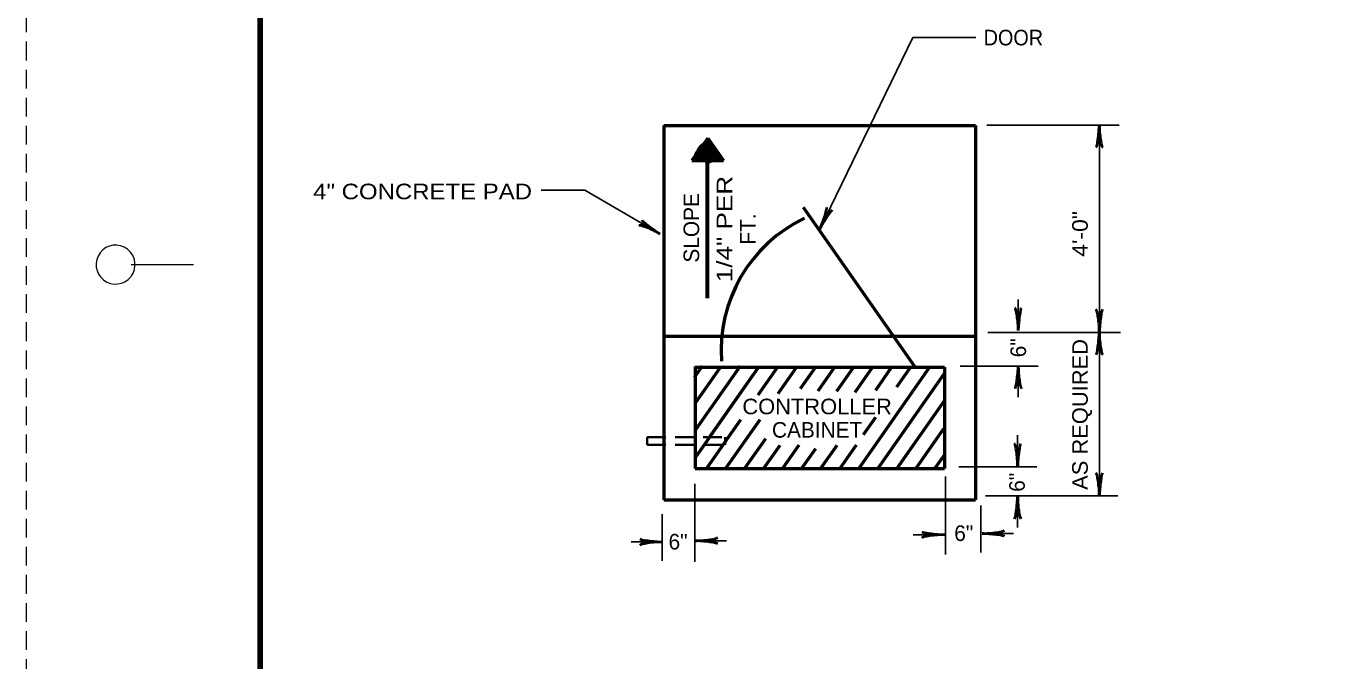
# Model space of a CAD drawing. Extents: x -560 to 120, y 26 to 466.
# Drawn here: x -559.8 to -392.1, y 112.8 to 194.2 of the extents above; entities that cross this region are included whole.
import ezdxf
from ezdxf.enums import TextEntityAlignment as Align

# ---------------------------------------------------------------- set-up
doc = ezdxf.new("R2010")
doc.units = 0
doc.header["$LTSCALE"] = 0.8
doc.linetypes.add('MEDIUM_DASHED', pattern=[4.5, 3, -1.5])
doc.layers.add('1', color=7, linetype='Continuous', lineweight=53)
doc.layers.add('61', color=7, linetype='Continuous', lineweight=35)

msp = doc.modelspace()

# ---------------------------------------------------------------- linework, layer by layer
at = {"layer": '1', "linetype": 'MEDIUM_DASHED', "lineweight": 13}
msp.add_line((-559.7809, 465.8427), (-559.8409, 25.8027), dxfattribs=at)
at = {"layer": '1'}
for p, q in [((-477.9601, 181.4815), (-477.9601, 133.4815)), ((-477.9601, 181.4815), (-472.0546, 181.4815)), ((-473.9601, 181.4815), (-473.9601, 181.3655)), ((-473.8417, 181.4815), (-437.9601, 181.4815)), ((-437.9601, 181.4815), (-437.9601, 133.4815)), ((-472.3459, 179.8789), (-474.3775, 176.9776)), ((-472.3459, 179.8789), (-470.3143, 176.9776)), ((-474.3775, 176.9776), (-470.3143, 176.9776)), ((-445.7124, 150.4778), (-460.0518, 170.9567)), ((-477.9601, 154.4815), (-437.9601, 154.4815)), ((-473.0564, 150.6275), (-474.0715, 149.1778)), ((-473.9601, 150.5942), (-473.9601, 150.4388)), ((-473.9601, 150.4815), (-473.8417, 150.4815)), ((-473.9601, 150.4815), (-441.9601, 150.4815)), ((-473.9601, 150.4815), (-473.9601, 137.4815)), ((-465.8339, 150.4815), (-473.9601, 138.8762)), ((-470.8374, 150.3097), (-473.941, 145.8773)), ((-468.1692, 150.6333), (-473.905, 142.4417)), ((-466.5309, 149.4861), (-472.2667, 141.2946)), ((-463.3923, 150.4815), (-465.9038, 146.895)), ((-460.9509, 150.4815), (-463.3357, 147.0756)), ((-458.5093, 150.4815), (-460.4595, 147.6964)), ((-456.0677, 150.4815), (-458.2222, 147.4047)), ((-453.6262, 150.4815), (-455.795, 147.3841)), ((-451.1846, 150.4815), (-453.4482, 147.2488)), ((-443.8601, 150.4815), (-452.9627, 137.4815)), ((-448.7431, 150.4815), (-450.8202, 147.5151)), ((-441.9601, 149.708), (-450.5212, 137.4815)), ((-446.3015, 150.4815), (-448.1046, 147.9064)), ((-441.9601, 150.4815), (-441.9601, 137.4815)), ((-441.9601, 146.2211), (-448.0796, 137.4815)), ((-468.1164, 143.7349), (-472.4951, 137.4815)), ((-465.6689, 143.7434), (-470.0535, 137.4815)), ((-450.8174, 144.032), (-452.373, 141.8105)), ((-464.9432, 141.2928), (-467.612, 137.4815)), ((-442.0678, 142.5806), (-445.6382, 137.4815)), ((-463.0967, 140.4432), (-465.1705, 137.4815)), ((-460.6257, 140.4852), (-462.7289, 137.4815)), ((-458.5198, 140.0057), (-460.2873, 137.4815)), ((-455.7641, 140.4545), (-457.8458, 137.4815)), ((-453.2858, 140.5069), (-455.4042, 137.4815)), ((-441.9601, 139.2473), (-443.1312, 137.5747)), ((-473.9601, 137.4815), (-441.9601, 137.4815)), ((-477.9601, 133.4815), (-437.9601, 133.4815))]:
    msp.add_line(p, q, dxfattribs=at)
at = {"layer": '1', "lineweight": 25}
for p, q in [((-436.5237, 181.5331), (-419.5237, 181.5331)), ((-432.4829, 155.1907), (-432.4829, 159.1907)), ((-436.3682, 154.9578), (-419.3682, 154.9578)), ((-439.9427, 150.6062), (-429.9427, 150.6062)), ((-432.4829, 146.6431), (-432.4829, 150.6431)), ((-432.5606, 137.7846), (-432.5606, 141.7846)), ((-440.0981, 137.7071), (-430.0981, 137.7071)), ((-441.8077, 136.4638), (-441.8077, 126.4637)), ((-473.9778, 135.5312), (-473.9778, 125.5312)), ((-437.3007, 132.7339), (-437.3007, 126.7339)), ((-436.6791, 133.9772), (-419.6791, 133.9772)), ((-432.5606, 129.9363), (-432.5606, 133.9363)), ((-478.1739, 131.646), (-478.1739, 125.646)), ((-478.1739, 128.0715), (-482.1739, 128.0715)), ((-469.9372, 128.2269), (-473.9372, 128.2269)), ((-441.9631, 129.004), (-445.9631, 129.004)), ((-433.1046, 129.1594), (-437.1046, 129.1594))]:
    msp.add_line(p, q, dxfattribs=at)
at = {"layer": '1', "lineweight": 60}
msp.add_line((-472.4237, 179.3572), (-472.4237, 159.3572), dxfattribs=at)
at = {"layer": '1', "linetype": 'MEDIUM_DASHED', "lineweight": 35}
for p, q in [((-480.1165, 141.5145), (-470.1165, 141.5145)), ((-480.1165, 141.5145), (-480.1165, 140.5145)), ((-470.1165, 141.5145), (-470.1165, 140.5145)), ((-480.1165, 140.5145), (-470.1165, 140.5145))]:
    msp.add_line(p, q, dxfattribs=at)
at = {"layer": '1', "lineweight": 25}
for points in [[(-457.9705, 168.2067), (-446.0037, 192.7618), (-437.9209, 192.7618)], [(-422.0704, 181.5722), (-422.0704, 154.9968), (-422.0704, 134.0139)], [(-478.4848, 167.5852), (-488.1203, 173.1799), (-493.7173, 173.1799)]]:
    msp.add_lwpolyline(points, dxfattribs=at)
at = {"layer": '1'}
msp.add_arc((-451.8151, 152.622), 18.8127, 115.56181, 184.16724, dxfattribs=at)
at = {"layer": '1', "lineweight": 40}
for centre, major_axis, ratio, start_param, end_param in [((-422.282, 180.4517), (-0.1757, -1.7565), 0.07063, 6.28230741, 8.55970261), ((-422.282, 180.4517), (-0.1757, -1.7565), 0.07063, 6.28230741, 8.55970261), ((-421.7941, 180.481), (-0.1562, 1.7857), 0.122415, 0.89635335, 3.14159265), ((-421.7941, 180.481), (-0.1562, 1.7857), 0.122415, 0.89635335, 3.14159265), ((-457.7408, 169.3087), (-0.6419, -1.6736), 0.122415, 0.89635335, 3.14159265), ((-457.2894, 169.1213), (0.9274, 1.502), 0.07063, 6.28230741, 8.55970261), ((-479.5672, 167.8942), (1.6227, -0.7616), 0.122415, 0.89635335, 3.14159265), ((-479.3476, 168.3308), (1.4308, -1.0339), 0.07063, 3.14071475, 5.41810995), ((-432.7592, 156.2819), (0.1562, -1.7857), 0.122415, 0.89635335, 3.14159265), ((-432.2713, 156.3112), (0.1757, 1.7565), 0.07063, 6.28230741, 8.55970261), ((-422.3467, 156.088), (0.1562, -1.7857), 0.122415, 0.89635335, 3.14159265), ((-421.8588, 156.1173), (0.1757, 1.7565), 0.07063, 6.28230741, 8.55970261), ((-422.282, 153.8763), (-0.1757, -1.7565), 0.07063, 6.28230741, 8.55970261), ((-421.7941, 153.9056), (-0.1562, 1.7857), 0.122415, 0.89635335, 3.14159265), ((-432.6945, 149.5226), (-0.1757, -1.7565), 0.07063, 6.28230741, 8.55970261), ((-432.2066, 149.5519), (-0.1562, 1.7857), 0.122415, 0.89635335, 3.14159265), ((-432.8369, 138.8758), (0.1562, -1.7857), 0.122415, 0.89635335, 3.14159265), ((-432.349, 138.9051), (0.1757, 1.7565), 0.07063, 6.28230741, 8.55970261), ((-422.3467, 135.1051), (0.1562, -1.7857), 0.122415, 0.89635335, 3.14159265), ((-421.8588, 135.1344), (0.1757, 1.7565), 0.07063, 6.28230741, 8.55970261), ((-432.7722, 132.8158), (-0.1757, -1.7565), 0.07063, 6.28230741, 8.55970261), ((-432.2843, 132.8451), (-0.1562, 1.7857), 0.122415, 0.89635335, 3.14159265), ((-443.0836, 129.2156), (1.7565, -0.1757), 0.07063, 3.14071475, 5.41810995), ((-436.0134, 129.4357), (-1.7857, -0.1562), 0.122415, 0.89635335, 3.14159265), ((-479.2651, 127.7952), (1.7857, 0.1562), 0.122415, 0.89635335, 3.14159265), ((-479.2944, 128.2831), (1.7565, -0.1757), 0.07063, 3.14071475, 5.41810995), ((-472.8167, 128.0153), (1.7565, -0.1757), 0.07063, 6.28230741, 8.55970261), ((-472.846, 128.5032), (-1.7857, -0.1562), 0.122415, 0.89635335, 3.14159265), ((-443.0543, 128.7277), (1.7857, 0.1562), 0.122415, 0.89635335, 3.14159265), ((-435.9841, 128.9478), (1.7565, -0.1757), 0.07063, 6.28230741, 8.55970261)]:
    msp.add_ellipse(centre, major_axis=major_axis, ratio=ratio, start_param=start_param, end_param=end_param, dxfattribs=at)
at = {"layer": '1'}
msp.add_spline([(-472.4237, 179.2796), (-472.4237, 179.0464), (-472.4237, 179.5127), (-472.346, 178.4248), (-472.5791, 178.4248), (-472.5791, 178.891), (-472.6568, 178.9688), (-472.9677, 178.4248), (-473.3562, 177.8032), (-473.4338, 177.2592), (-473.5892, 177.2592), (-473.7447, 177.2592), (-473.9001, 177.1815), (-473.5892, 177.7254), (-473.9001, 177.2592), (-472.7345, 179.0464), (-472.1906, 178.5025), (-471.9574, 178.6579), (-471.6467, 178.1917), (-471.5689, 177.9586), (-471.8021, 178.3471), (-472.346, 178.8133), (-471.9574, 178.9688), (-471.8021, 178.7356), (-471.6467, 178.0362), (-471.4912, 177.8032), (-471.2581, 177.3369), (-471.1027, 177.1815), (-471.2581, 177.8808), (-471.5689, 178.114), (-471.025, 177.4147), (-470.9472, 177.2592), (-471.6467, 177.4147), (-472.2682, 177.8032), (-472.5014, 178.114), (-472.6568, 178.1917), (-472.7345, 177.8808), (-472.8123, 177.4923), (-472.9677, 177.4147), (-472.9677, 177.3369), (-472.0352, 178.1917), (-472.8899, 178.0362), (-472.9677, 177.4147), (-472.5791, 177.4923), (-472.1906, 177.4923), (-471.8021, 177.9586), (-471.7243, 177.8808), (-472.2682, 177.57), (-472.1906, 177.1038), (-471.9574, 177.1038), (-471.8798, 177.6478), (-473.1231, 177.4923), (-473.2784, 176.9484), (-472.9677, 177.3369), (-472.8123, 177.1038), (-471.4912, 177.3369), (-471.4912, 177.57), (-471.8021, 178.2694), (-472.1128, 178.5025), (-472.0352, 178.0362), (-471.5689, 178.0362), (-472.4237, 178.5025), (-472.8123, 178.2694), (-472.2682, 178.0362), (-472.1906, 179.1242), (-471.5689, 178.114), (-471.2581, 177.57), (-471.025, 177.3369), (-471.7243, 177.8032), (-472.4237, 178.5025), (-470.7918, 177.0261), (-471.4912, 178.2694), (-472.4237, 178.3471), (-472.4237, 178.7356), (-472.7345, 177.4923), (-472.8123, 177.3369)], degree=3, dxfattribs=at)
at = {"layer": '61', "lineweight": 13}
msp.add_line((-546.3609, 163.6627), (-538.3609, 163.6627), dxfattribs=at)
at = {"layer": '61', "lineweight": 158}
msp.add_lwpolyline([(109.2591, 455.8427), (-529.7809, 455.8427), (-529.7809, 35.8227)], dxfattribs=at)
at = {"layer": '61', "lineweight": 13}
msp.add_arc((-548.3632, 163.644), 2.5, 322.67175, 321.71615, dxfattribs=at)

# ---------------------------------------------------------------- texts
at = {"layer": '1'}
for s, width, p in [('DOOR', 0.95, (-433.1045, 191.7618)), ('4" CONCRETE PAD', 1.15, (-508.9454, 172.0245)), ('CONTROLLER', 1.05, (-458.3006, 144.4506))]:
    msp.add_text(s, height=2, dxfattribs=dict(at, width=width)).set_placement(p, align=Align.CENTER)
for s, width, p in [('1/4" PER', 1.25, (-469.1939, 168.2067)), ('4\'-0"', 1.1, (-423.557, 167.5852)), ('AS REQUIRED', 1.05, (-423.557, 144.4288))]:
    msp.add_text(s, height=2, rotation=90, dxfattribs=dict(at, width=width)).set_placement(p, align=Align.CENTER)
for s, p in [('SLOPE', (-473.4442, 168.3621)), ('FT.', (-466.1939, 168.2068)), ('6"', (-431.483, 152.9765)), ('6"', (-431.6384, 135.7258))]:
    msp.add_text(s, height=2, rotation=90, dxfattribs=at).set_placement(p, align=Align.CENTER)
for s, p in [('CABINET', (-458.3006, 141.4506)), ('6"', (-439.4765, 128.1985)), ('6"', (-476.1535, 127.1106))]:
    msp.add_text(s, height=2, dxfattribs=at).set_placement(p, align=Align.CENTER)

doc.saveas('drawing.dxf')
